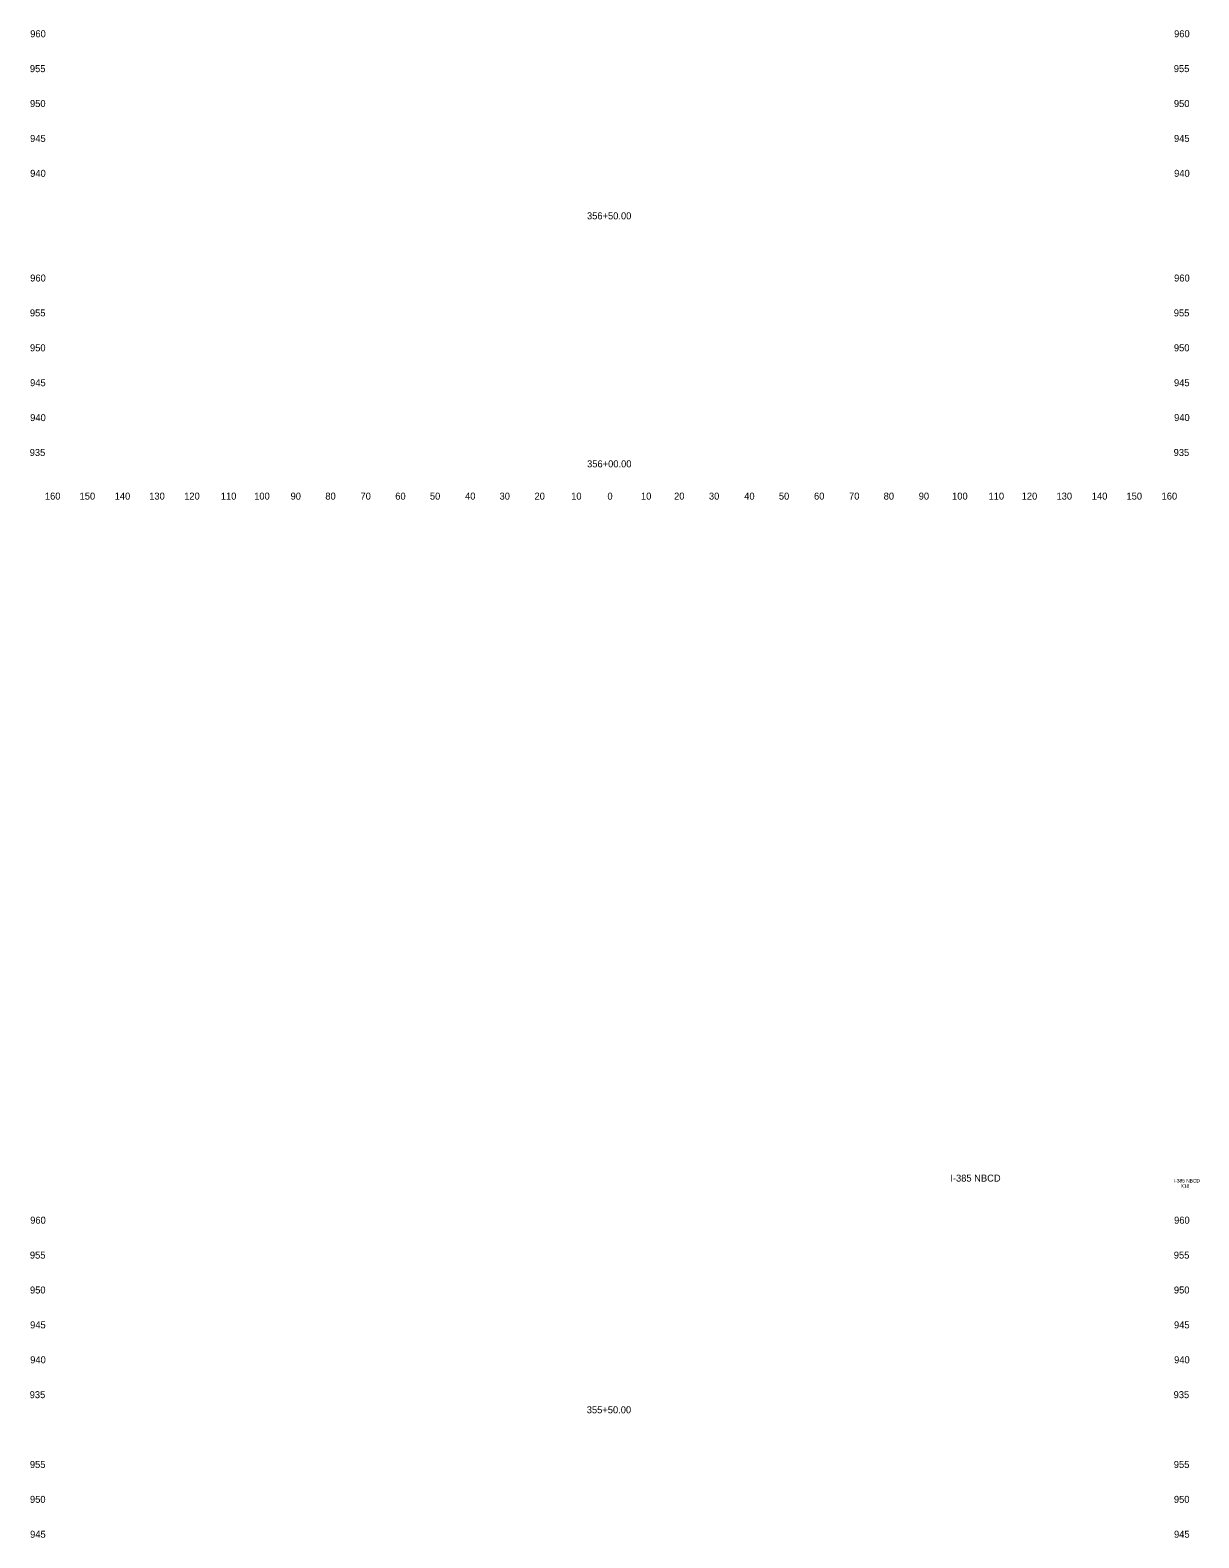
# Model space of a CAD drawing. Extents: x 4994 to 7391, y 4997 to 8804.
# Drawn here: x 5508.9 to 5843.8, y 7900 to 8332 of the extents above; entities that cross this region are included whole.
import ezdxf

# ---------------------------------------------------------------- set-up
doc = ezdxf.new("R2010")
doc.units = 0
for name, color, linetype in [('RD_SHT_ID', 7, 'Continuous'), ('RD_XS_TX_Offset', 7, 'Continuous'), ('RD_XS_TX_Station', 7, 'Continuous')]:
    doc.layers.add(name, color=color, linetype=linetype)

msp = doc.modelspace()

# ---------------------------------------------------------------- texts
at = {"layer": 'RD_SHT_ID'}
for s, height, p in [('I-385 NBCD', 2, (5772.56, 8002.06)), ('I-385 NBCD', 1, (5836.63, 8001.8)), ('X18', 1, (5838.57, 8000.3))]:
    msp.add_text(s, height=height, dxfattribs=at).set_placement(p)
at = {"layer": 'RD_XS_TX_Offset'}
for s, p in [('960', (5508.89, 8330)), ('960', (5836.69, 8330)), ('955', (5508.8, 8320)), ('955', (5836.6, 8320)), ('950', (5508.83, 8310)), ('950', (5836.63, 8310)), ('945', (5508.86, 8300)), ('945', (5836.66, 8300)), ('940', (5508.89, 8290)), ('940', (5836.69, 8290)), ('960', (5508.89, 8260)), ('960', (5836.69, 8260)), ('955', (5508.8, 8250)), ('955', (5836.6, 8250)), ('950', (5508.83, 8240)), ('950', (5836.63, 8240)), ('945', (5508.86, 8230)), ('945', (5836.66, 8230)), ('940', (5508.89, 8220)), ('940', (5836.69, 8220)), ('935', (5508.75, 8210)), ('935', (5836.55, 8210)), ('160', (5513.1, 8197.5)), ('150', (5523.04, 8197.5)), ('140', (5533.1, 8197.5)), ('130', (5542.99, 8197.5)), ('120', (5553.01, 8197.5)), ('110', (5563.51, 8197.5)), ('100', (5573.07, 8197.5)), ('90', (5583.5, 8197.5)), ('80', (5593.46, 8197.5)), ('70', (5603.54, 8197.5)), ('60', (5613.5, 8197.5)), ('50', (5623.43, 8197.5)), ('40', (5633.5, 8197.5)), ('30', (5643.39, 8197.5)), ('20', (5653.4, 8197.5)), ('10', (5663.91, 8197.5)), ('0', (5674.3, 8197.5)), ('0', (5674.3, 8197.5)), ('10', (5683.91, 8197.5)), ('20', (5693.4, 8197.5)), ('30', (5703.39, 8197.5)), ('40', (5713.5, 8197.5)), ('50', (5723.43, 8197.5)), ('60', (5733.5, 8197.5)), ('70', (5743.54, 8197.5)), ('80', (5753.46, 8197.5)), ('90', (5763.5, 8197.5)), ('100', (5773.07, 8197.5)), ('110', (5783.51, 8197.5)), ('120', (5793.01, 8197.5)), ('130', (5802.99, 8197.5)), ('140', (5813.1, 8197.5)), ('150', (5823.04, 8197.5)), ('160', (5833.1, 8197.5)), ('960', (5508.89, 7990)), ('960', (5836.69, 7990)), ('955', (5508.8, 7980)), ('955', (5836.6, 7980)), ('950', (5508.83, 7970)), ('950', (5836.63, 7970)), ('945', (5508.86, 7960)), ('945', (5836.66, 7960)), ('940', (5508.89, 7950)), ('940', (5836.69, 7950)), ('935', (5508.75, 7940)), ('935', (5836.55, 7940)), ('955', (5508.8, 7920)), ('955', (5836.6, 7920)), ('950', (5508.83, 7910)), ('950', (5836.63, 7910)), ('945', (5508.86, 7900)), ('945', (5836.66, 7900))]:
    msp.add_text(s, height=2, dxfattribs=at).set_placement(p)
at = {"layer": 'RD_XS_TX_Station'}
for s, p in [('356+50.00', (5668.44, 8277.82)), ('356+00.00', (5668.47, 8206.75)), ('355+50.00', (5668.38, 7935.67))]:
    msp.add_text(s, height=2, dxfattribs=at).set_placement(p)

doc.saveas('drawing.dxf')
